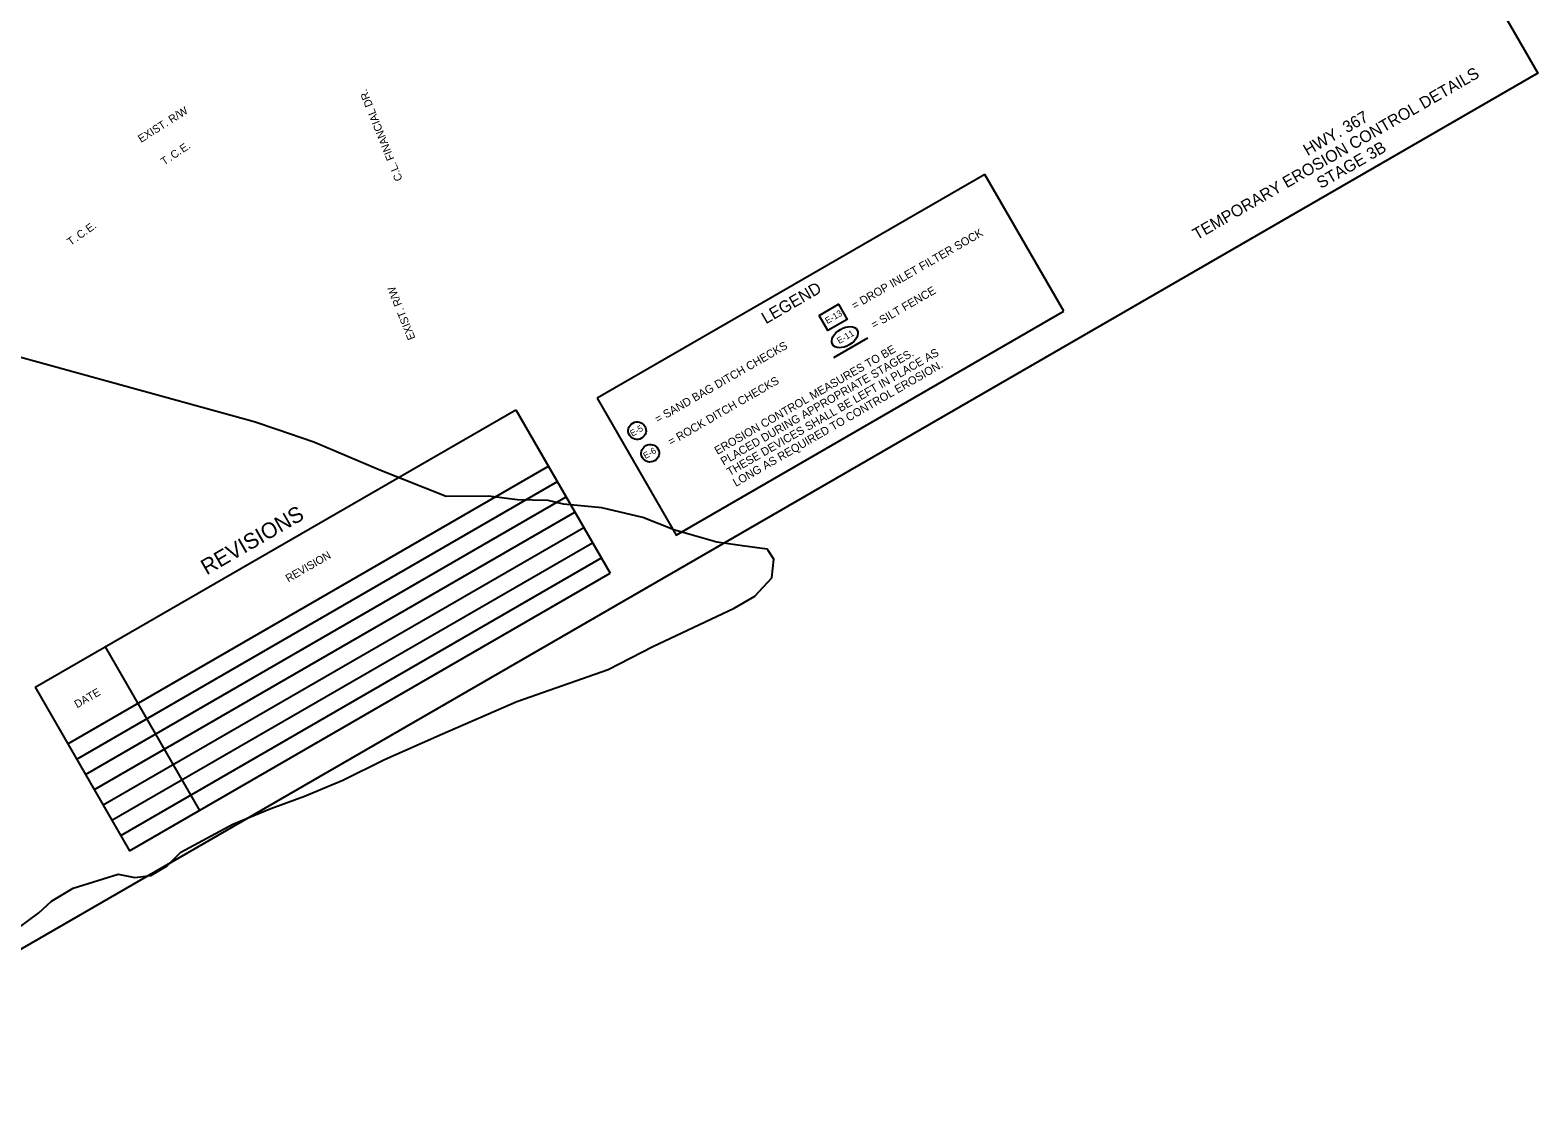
# Model space of a CAD drawing. Extents: x 1293524 to 1295623, y 222963 to 224839.
# Drawn here: x 1294272 to 1295427, y 222963 to 223794 of the extents above; entities that cross this region are included whole.
import ezdxf

# ---------------------------------------------------------------- set-up
doc = ezdxf.new("R2010")
doc.units = 0
for name, color, linetype in [('1', 7, 'Continuous'), ('10Tan10', 7, 'Continuous'), ('19', 7, 'Continuous'), ('60', 7, 'Continuous'), ('Default', 7, 'Continuous'), ('G-No Plot-Border-1', 7, 'Continuous'), ('Level 1', 7, 'Continuous'), ('Level 44', 7, 'Continuous'), ('R_Draft', 7, 'Continuous'), ('S_TREE', 7, 'Continuous')]:
    doc.layers.add(name, color=color, linetype=linetype)

msp = doc.modelspace()

# ---------------------------------------------------------------- linework, layer by layer
at = {"layer": '1'}
for p, q in [((1295003, 223683), (1294706.2, 223511.7)), ((1295063.5, 223578.2), (1295003, 223683))]:
    msp.add_line(p, q, dxfattribs=at)
msp.add_lwpolyline([(1294706.2, 223511.7), (1294766.7, 223406.8), (1295063.5, 223578.2)], dxfattribs=at)
at = {"layer": '19'}
for p, q in [((1294275.8, 223290.3), (1294643.9, 223502.8)), ((1294643.9, 223502.8), (1294716.2, 223377.6)), ((1294300.8, 223247), (1294668.9, 223459.5)), ((1294307.6, 223235.3), (1294675.7, 223447.8)), ((1294314.3, 223223.6), (1294682.4, 223436.1)), ((1294321.1, 223211.9), (1294689.2, 223424.4)), ((1294321.1, 223211.9), (1294689.2, 223424.4)), ((1294327.8, 223200.2), (1294695.9, 223412.7)), ((1294334.6, 223188.5), (1294702.7, 223401)), ((1294341.3, 223176.8), (1294709.4, 223389.3)), ((1294348.1, 223165.1), (1294716.2, 223377.6)), ((1294329.4, 223321.2), (1294401.6, 223196)), ((1294275.8, 223290.3), (1294348.1, 223165.1))]:
    msp.add_line(p, q, dxfattribs=at)
at = {"layer": 'G-No Plot-Border-1'}
msp.add_lwpolyline([(1294045, 222962.9), (1293523.9, 223865.5), (1294561.4, 224464.5), (1294586.2, 224421.6), (1294757.9, 224520.8), (1294765.6, 224507.3), (1294827.6, 224543.1), (1294901.4, 224415.4), (1295011.8, 224479.1), (1295426.7, 223760.5)], close=True, dxfattribs=at)
msp.add_lwpolyline([(1294045, 222962.9), (1293523.9, 223865.5), (1294561.4, 224464.5), (1294586.2, 224421.6), (1294757.9, 224520.8), (1294765.6, 224507.3), (1294827.6, 224543.1), (1294901.4, 224415.4), (1295011.8, 224479.1), (1295426.7, 223760.5)], close=True, dxfattribs=at)
msp.add_lwpolyline([(1294045, 222962.9), (1293523.9, 223865.5), (1294561.4, 224464.5), (1294586.2, 224421.6), (1294757.9, 224520.8), (1294765.6, 224507.3), (1294827.6, 224543.1), (1294901.4, 224415.4), (1295011.8, 224479.1), (1295426.7, 223760.5)], close=True, dxfattribs=at)
msp.add_lwpolyline([(1294045, 222962.9), (1293523.9, 223865.5), (1294561.4, 224464.5), (1294586.2, 224421.6), (1294757.9, 224520.8), (1294765.6, 224507.3), (1294827.6, 224543.1), (1294901.4, 224415.4), (1295011.8, 224479.1), (1295426.7, 223760.5)], close=True, dxfattribs=at)
at = {"layer": 'Level 1'}
msp.add_lwpolyline([(1294876.2, 223575), (1294891, 223583.6), (1294897.7, 223572), (1294882.9, 223563.4)], close=True, dxfattribs=at)
for centre, major_axis, ratio in [((1294895.9, 223558.4), (9.49, 5.48), 0.622952), ((1294736.8, 223486.8), (-5.96, -3.44), 0.97521), ((1294746.8, 223469.5), (-5.96, -3.44), 0.97521)]:
    msp.add_ellipse(centre, major_axis=major_axis, ratio=ratio, dxfattribs=at)
at = {"layer": 'Level 44'}
msp.add_lwpolyline([(1294887.5, 223542.8), (1294913.6, 223557.9)], dxfattribs=at)
at = {"layer": 'S_TREE'}
msp.add_lwpolyline([(1294255.9, 223100.7), (1294278.6, 223117.6), (1294288.4, 223126.5), (1294304.9, 223136.4), (1294339.3, 223147.2), (1294352.2, 223144.7), (1294364.3, 223146.2), (1294376.9, 223153.6), (1294387.4, 223164.1), (1294427.1, 223185.4), (1294456.2, 223197.5), (1294482.1, 223206.9), (1294511.5, 223219.1), (1294543.4, 223235), (1294587.7, 223254.7), (1294644.8, 223279.3), (1294714.6, 223304), (1294748.8, 223321.6), (1294811.1, 223350.9), (1294826.9, 223360.1), (1294840.1, 223374.1), (1294841.4, 223388.3), (1294837.1, 223395), (1294836.4, 223396), (1294817.4, 223398.6), (1294797.8, 223401.3), (1294765.6, 223410.7), (1294741.1, 223420.2), (1294709.9, 223427.8), (1294680.4, 223430.5), (1294668.7, 223433.4), (1294645.1, 223433.9), (1294623.1, 223436.6), (1294590.5, 223436.4), (1294539.8, 223456.6), (1294489.3, 223478), (1294460.8, 223487.6), (1294443.5, 223493.6), (1294098.9, 223588.6)], dxfattribs=at)
msp.add_lwpolyline([(1294255.9, 223100.7), (1294278.6, 223117.6), (1294288.4, 223126.5), (1294304.9, 223136.4), (1294339.3, 223147.2), (1294352.2, 223144.7), (1294364.3, 223146.2), (1294376.9, 223153.6), (1294387.4, 223164.1), (1294427.1, 223185.4), (1294456.2, 223197.5), (1294482.1, 223206.9), (1294511.5, 223219.1), (1294543.4, 223235), (1294587.7, 223254.7), (1294644.8, 223279.3), (1294714.6, 223304), (1294748.8, 223321.6), (1294811.1, 223350.9), (1294826.9, 223360.1), (1294840.1, 223374.1), (1294841.4, 223388.3), (1294837.1, 223395), (1294836.4, 223396), (1294817.4, 223398.6), (1294797.8, 223401.3), (1294765.6, 223410.7), (1294741.1, 223420.2), (1294709.9, 223427.8), (1294680.4, 223430.5), (1294668.7, 223433.4), (1294645.1, 223433.9), (1294623.1, 223436.6), (1294590.5, 223436.4), (1294539.8, 223456.6), (1294489.3, 223478), (1294460.8, 223487.6), (1294443.5, 223493.6), (1294098.9, 223588.6)], dxfattribs=at)

# ---------------------------------------------------------------- texts
at = {"layer": '10Tan10'}
for rotation, p in [(32.4263, (1294356.9, 223707.1)), (111.7954, (1294567.1, 223557.7))]:
    msp.add_text('EXIST. R/W', height=6, rotation=rotation, dxfattribs=at).set_placement(p)
at = {"layer": '19'}
for s, height, p in [('REVISIONS', 12, (1294407.1, 223375.9)), ('REVISION', 6, (1294469.7, 223370.5)), ('DATE', 6, (1294307.9, 223274.1))]:
    msp.add_text(s, height=height, rotation=30.0001, dxfattribs=at).set_placement(p)
at = {"layer": '60'}
for s, p in [('TEMPORARY EROSION CONTROL DETAILS', (1295165.5, 223632.5)), ('HWY. 367', (1295250.3, 223697)), ('STAGE 3B', (1295260.5, 223671.8))]:
    msp.add_text(s, height=9, rotation=30, dxfattribs=at).set_placement(p)
at = {"layer": 'Default'}
msp.add_text('C.L. FINANCIAL DR.', height=6, rotation=111.8333, dxfattribs=at).set_placement((1294557.3, 223679.3))
at = {"layer": 'Level 1'}
for s, height, p in [('= DROP INLET FILTER SOCK', 6.25, (1294903.3, 223579.3)), ('= SILT FENCE', 6.25, (1294918.2, 223564.6)), ('E-13', 4.88, (1294882.5, 223568.4)), ('E-11 ', 4.88, (1294891.6, 223553.1)), ('= SAND BAG DITCH CHECKS', 6.25, (1294752.7, 223492.4)), ('EROSION CONTROL MEASURES TO BE', 6.25, (1294798.3, 223468.2)), ('PLACED DURING APPROPRIATE STAGES. ', 6.25, (1294803, 223460)), ('THESE DEVICES SHALL BE LEFT IN PLACE AS ', 6.25, (1294807.7, 223451.9)), ('LONG AS REQUIRED TO CONTROL EROSION.', 6.25, (1294812.4, 223443.7)), ('= ROCK DITCH CHECKS', 6.25, (1294762.7, 223475.1)), ('E-5 ', 4.88, (1294733.1, 223482.1)), ('E-6 ', 4.88, (1294743.2, 223465))]:
    msp.add_text(s, height=height, rotation=30.0001, dxfattribs=at).set_placement(p)
at = {"layer": 'Level 44'}
msp.add_text('LEGEND', height=9.14, rotation=30.0001, dxfattribs=at).set_placement((1294835.4, 223568.2))
at = {"layer": 'R_Draft'}
for s, rotation, p in [('E', 34.0013, (1294389, 223699.4)), ('T', 34.0013, (1294374.6, 223689.7)), ('C', 34.0013, (1294381.9, 223694.6)), ('.', 34.0013, (1294386.6, 223697.8)), ('.', 34.0013, (1294393.5, 223702.5)), ('.', 34.0013, (1294379.5, 223693)), ('C', 35.3335, (1294310.1, 223633.3)), ('E', 35.3335, (1294317.1, 223638.2)), ('.', 35.3335, (1294314.7, 223636.5)), ('.', 35.3335, (1294321.5, 223641.4)), ('T', 35.3335, (1294302.9, 223628.2)), ('.', 35.3335, (1294307.7, 223631.6))]:
    msp.add_text(s, height=6, rotation=rotation, dxfattribs=at).set_placement(p)

doc.saveas('drawing.dxf')
